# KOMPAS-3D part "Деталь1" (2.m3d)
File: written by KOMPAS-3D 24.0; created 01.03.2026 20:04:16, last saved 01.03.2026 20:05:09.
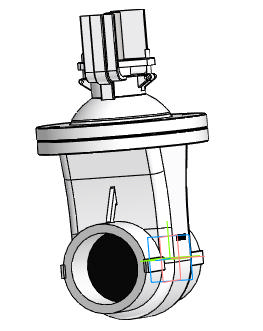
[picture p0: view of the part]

Document properties: Автор: R2D2; Полное имя файла: E:\Работа\Зайцев\GVWR3131M-2W-F-S Задвижка клиновая с выдвижным штоком DN.ru Ду50-200 Ру63\DN80\исходные материалы\2.m3d

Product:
- Body: Твердое тело1  | qty 1
    Масса: 0.177387
- Part/product: Деталь1
    Масса: 0.177387
    additional columns: Типовые

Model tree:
1. Твердое тело1  (labels: Твердое тело1)
2. Эскиз:1
3. Элемент выдавливания:2
     Расстояние 1 = 500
